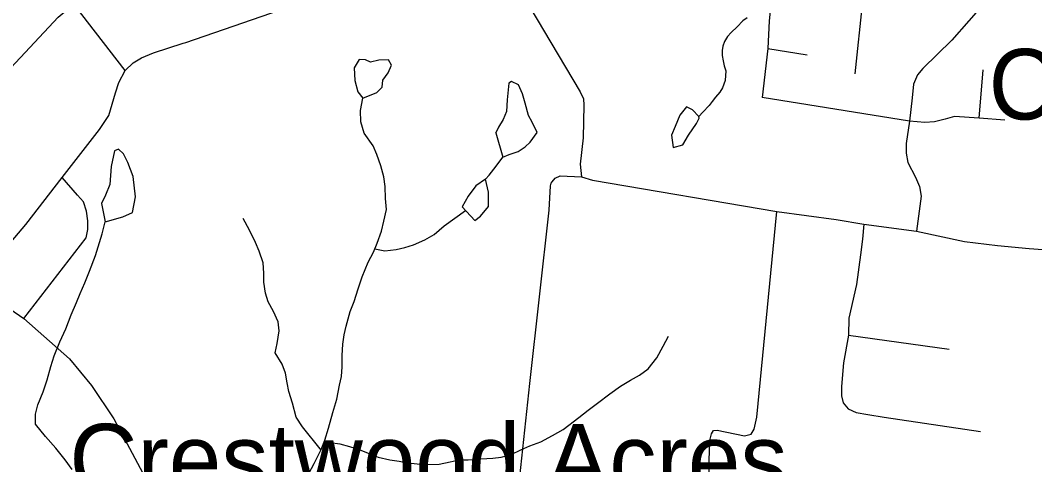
# Model space of a CAD drawing. Extents: x 0 to 69.5, y -4.5 to 22.
# Drawn here: x 2.379 to 3.515, y 16.285 to 16.783 of the extents above; entities that cross this region are included whole.
import ezdxf

# ---------------------------------------------------------------- set-up
doc = ezdxf.new("R2010")
doc.units = 0
for name, color, linetype in [('GM_X_County_Road', 7, 'Continuous'), ('GM_X_Interstate_Route', 7, 'Continuous'), ('GM_X_Minor_Lake', 7, 'Continuous'), ('GM_X_Minor_River', 7, 'Continuous'), ('GM_X_Township_Subdivision', 7, 'Continuous'), ('GM_X_Unincorporated_Text', 7, 'Continuous')]:
    doc.layers.add(name, color=color, linetype=linetype)

msp = doc.modelspace()

# ---------------------------------------------------------------- linework, layer by layer
at = {"layer": 'GM_X_County_Road'}
for points in [[(2.5645, 16.7579), (2.6921, 16.8018), (2.7129, 16.8072), (2.7415, 16.8122), (2.8434, 16.8208), (2.8888, 16.8307), (2.925, 16.8393)], [(2.925, 16.8393), (3.0063, 16.7023), (3.0099, 16.6947), (3.0101, 16.6874), (3.0094, 16.6508), (3.0062, 16.6215), (3.0077, 16.6072)], [(2.4966, 16.7263), (2.4393, 16.8007), (2.4357, 16.8056)], [(2.3395, 16.5036), (2.3546, 16.5175), (2.3853, 16.5537), (2.4262, 16.6065), (2.4679, 16.6603), (2.4783, 16.676), (2.4859, 16.7014), (2.4895, 16.7128), (2.4966, 16.7263), (2.5057, 16.7348), (2.5149, 16.7406), (2.5283, 16.7461), (2.5618, 16.757), (2.5645, 16.7579)], [(2.3831, 16.4487), (2.4531, 16.5388), (2.4547, 16.5483), (2.4548, 16.5581), (2.4534, 16.5688), (2.4501, 16.5791), (2.4433, 16.5867), (2.4262, 16.6065)], [(2.8559, 15.3242), (2.8828, 15.5776), (2.8823, 15.5871), (2.88, 15.6009), (2.8808, 15.6183), (2.8941, 15.7652), (2.913, 15.9963), (2.9286, 16.1743), (2.9306, 16.1979), (2.9499, 16.3756), (2.9714, 16.57), (2.9729, 16.5972), (2.9738, 16.6003), (2.9747, 16.6018), (2.978, 16.6059), (2.9836, 16.6083), (3.0077, 16.6072)], [(3.0077, 16.6072), (3.0199, 16.6034), (3.2263, 16.5685), (3.2928, 16.5595), (3.3237, 16.5541), (3.3826, 16.5464), (3.4363, 16.5348), (3.4732, 16.5304), (3.5089, 16.527), (3.5443, 16.5245), (3.6987, 16.5072), (3.6996, 16.5071)], [(3.2878, 15.9702), (3.2906, 16.01), (3.287, 16.0204), (3.2811, 16.0285), (3.1838, 16.1424), (3.1651, 16.1641), (3.1565, 16.1802), (3.1523, 16.1945), (3.1498, 16.2167), (3.1509, 16.3102), (3.153, 16.3194), (3.1554, 16.3229), (3.1594, 16.3234), (3.1901, 16.3171), (3.1974, 16.3189), (3.2011, 16.3245), (3.2039, 16.3381), (3.2263, 16.5685)], [(2.2074, 16.5345), (2.2273, 16.5312), (2.2755, 16.511), (2.3238, 16.4892), (2.3831, 16.4487), (2.4345, 16.4035), (2.4589, 16.3735), (2.484, 16.336), (2.5458, 16.2199), (2.6419, 16.0249), (2.6836, 15.948), (2.7291, 15.8843), (2.758, 15.8531), (2.7648, 15.8462)]]:
    msp.add_lwpolyline(points, dxfattribs=at)
at = {"layer": 'GM_X_Interstate_Route'}
msp.add_lwpolyline([(2.181, 16.4629), (2.2273, 16.5312), (2.2674, 16.589), (2.34, 16.6943), (2.3633, 16.7237), (2.4215, 16.7861), (2.4393, 16.8007), (2.4586, 16.8179), (2.4894, 16.8393), (2.7155, 16.9908), (2.8497, 17.0804), (2.9292, 17.1425), (3.0025, 17.2108), (3.0522, 17.2646), (3.1203, 17.3605), (3.2374, 17.5377), (3.2788, 17.5999), (3.3097, 17.642), (3.3406, 17.6772), (3.3886, 17.7251), (3.5019, 17.8134), (3.5855, 17.8769), (3.6539, 17.9292), (3.721, 17.9807)], dxfattribs=at)
at = {"layer": 'GM_X_Minor_Lake'}
for points in [[(2.7627, 16.6952), (2.7784, 16.7018), (2.7843, 16.7077), (2.7852, 16.7157), (2.7911, 16.7239), (2.7947, 16.7322), (2.7914, 16.7383), (2.7808, 16.7378), (2.7712, 16.7358), (2.7659, 16.7382), (2.7587, 16.7387), (2.7532, 16.7293), (2.754, 16.7152)], [(2.754, 16.7152), (2.7572, 16.7026), (2.7627, 16.6952)], [(2.9196, 16.6293), (2.9265, 16.6324), (2.9368, 16.6356), (2.9446, 16.6407), (2.95, 16.6459), (2.9578, 16.6568), (2.9524, 16.6683), (2.9484, 16.676), (2.9445, 16.6897), (2.9417, 16.7001), (2.937, 16.7104), (2.9291, 16.714), (2.9264, 16.7122), (2.9245, 16.6936), (2.9238, 16.6803), (2.9198, 16.6713), (2.9147, 16.6627), (2.9115, 16.6563)], [(2.9196, 16.6293), (2.9265, 16.6324), (2.9368, 16.6356), (2.9446, 16.6407), (2.95, 16.6459), (2.9578, 16.6568), (2.9524, 16.6683), (2.9484, 16.676), (2.9445, 16.6897), (2.9417, 16.7001), (2.937, 16.7104), (2.9291, 16.714), (2.9264, 16.7122), (2.9245, 16.6936), (2.9238, 16.6803), (2.9198, 16.6713), (2.9147, 16.6627), (2.9116, 16.6566)], [(3.139, 16.6747), (3.132, 16.6822), (3.1252, 16.6857), (3.1178, 16.6764)], [(3.1178, 16.6764), (3.1126, 16.6636), (3.1085, 16.6538), (3.1101, 16.6401), (3.1212, 16.6429), (3.1275, 16.6538), (3.1362, 16.6669), (3.1393, 16.6729), (3.139, 16.6747)], [(2.9116, 16.6566), (2.9196, 16.6293)], [(2.4743, 16.5569), (2.4939, 16.5626), (2.505, 16.5673), (2.5084, 16.5847), (2.5055, 16.6076), (2.4998, 16.6233), (2.4947, 16.6329), (2.4891, 16.6383), (2.4849, 16.6365), (2.4811, 16.6188), (2.4795, 16.5987), (2.4747, 16.5866), (2.4703, 16.5772)], [(2.8893, 16.5971), (2.8807, 16.5856), (2.8739, 16.5736), (2.888, 16.5584), (2.8946, 16.5632), (2.9036, 16.574), (2.9035, 16.59), (2.9001, 16.6045)], [(2.9001, 16.6045), (2.8893, 16.5971)], [(2.4703, 16.5772), (2.4743, 16.5569)]]:
    msp.add_lwpolyline(points, dxfattribs=at)
at = {"layer": 'GM_X_Minor_River'}
for points in [[(3.193, 16.7854), (3.1883, 16.7821), (3.182, 16.7754), (3.175, 16.7691), (3.1711, 16.7643), (3.1679, 16.7587), (3.1659, 16.7538), (3.165, 16.7488), (3.1652, 16.7431), (3.1662, 16.737), (3.1675, 16.7316), (3.1693, 16.7259), (3.1686, 16.7152), (3.1654, 16.7069), (3.1626, 16.7021), (3.1578, 16.6965), (3.1539, 16.6916), (3.1504, 16.6872), (3.1433, 16.6798), (3.139, 16.6747)], [(2.7023, 16.2748), (2.7083, 16.2861), (2.7163, 16.3019), (2.7203, 16.3121), (2.7244, 16.3257), (2.7291, 16.3434), (2.7336, 16.3581), (2.7366, 16.3737), (2.7388, 16.3835), (2.7398, 16.3945), (2.7397, 16.4071), (2.7404, 16.4196), (2.7418, 16.4302), (2.744, 16.44), (2.7485, 16.4563), (2.753, 16.4676), (2.7575, 16.4819), (2.762, 16.4951), (2.7689, 16.5117), (2.7749, 16.523), (2.7789, 16.5331), (2.7838, 16.5463), (2.7863, 16.5577), (2.7893, 16.5705), (2.7881, 16.5831), (2.7877, 16.5964), (2.7864, 16.6071), (2.7829, 16.6197), (2.7783, 16.6324), (2.7743, 16.642), (2.7644, 16.656), (2.7606, 16.669), (2.7601, 16.6815), (2.7627, 16.6952)], [(2.9001, 16.6045), (2.9043, 16.6092), (2.9121, 16.6193), (2.9196, 16.6293)], [(2.7159, 16.3011), (2.7151, 16.3027), (2.6952, 16.3271), (2.6883, 16.3379), (2.6841, 16.3536), (2.6798, 16.3667), (2.6782, 16.3766), (2.6762, 16.3873), (2.6726, 16.3973), (2.6646, 16.41), (2.6667, 16.4206), (2.669, 16.4346), (2.6681, 16.4449), (2.6627, 16.4565), (2.6568, 16.4673), (2.6537, 16.4769), (2.652, 16.4891), (2.6519, 16.4993), (2.6511, 16.5108), (2.6468, 16.5238), (2.6425, 16.5338), (2.636, 16.5473), (2.6287, 16.5604)], [(2.7763, 16.5265), (2.7874, 16.5242), (2.8, 16.5258), (2.8099, 16.5282), (2.8195, 16.531), (2.8322, 16.5368), (2.8426, 16.5426), (2.8538, 16.5522), (2.8778, 16.5695)], [(2.4372, 16.2794), (2.4295, 16.2903), (2.4191, 16.3031), (2.4073, 16.3163), (2.3962, 16.3302), (2.3961, 16.3413), (2.399, 16.3519), (2.4047, 16.3665), (2.4092, 16.3798), (2.4134, 16.3949), (2.4171, 16.4066), (2.4236, 16.4224), (2.4304, 16.437), (2.4361, 16.4525), (2.4421, 16.4664), (2.4462, 16.4766), (2.4514, 16.4883), (2.4566, 16.5014), (2.4635, 16.5191), (2.4681, 16.5335), (2.471, 16.5433), (2.4743, 16.5569)], [(2.7198, 16.3108), (2.7263, 16.3096), (2.7369, 16.3082), (2.7479, 16.3053), (2.7588, 16.3016), (2.7686, 16.2976), (2.7799, 16.2931), (2.7931, 16.2901), (2.8034, 16.2887), (2.8132, 16.287), (2.8238, 16.2856), (2.8348, 16.2849), (2.8481, 16.2854), (2.8607, 16.2881), (2.8706, 16.2901), (2.8809, 16.2903), (2.895, 16.2914), (2.9083, 16.2919), (2.9178, 16.2932), (2.9289, 16.2963), (2.9397, 16.3014), (2.9497, 16.3057), (2.962, 16.3103), (2.975, 16.3173), (2.987, 16.3242), (3.0048, 16.3378), (3.0149, 16.3459), (3.0257, 16.3537), (3.0393, 16.364), (3.0513, 16.3728), (3.0624, 16.3794), (3.0725, 16.3849), (3.0821, 16.3922), (3.0919, 16.4045), (3.0991, 16.4177), (3.1051, 16.4289)]]:
    msp.add_lwpolyline(points, dxfattribs=at)
at = {"layer": 'GM_X_Township_Subdivision'}
for points in [[(3.2267, 16.9013), (3.2264, 16.898), (3.2266, 16.87), (3.2207, 16.8119), (3.2179, 16.7821), (3.2161, 16.7511), (3.2099, 16.6961)], [(3.8766, 16.8608), (3.8386, 16.8639), (3.6602, 16.8815), (3.5812, 16.8884), (3.5665, 16.887), (3.553, 16.8832), (3.541, 16.877), (3.5216, 16.8628), (3.4605, 16.8035), (3.4221, 16.7604), (3.3897, 16.7285), (3.3838, 16.7214), (3.3793, 16.711), (3.3779, 16.6956), (3.3748, 16.6696), (3.3712, 16.6447), (3.371, 16.6339), (3.3731, 16.6233), (3.3815, 16.607), (3.3861, 16.5965), (3.388, 16.5857), (3.3826, 16.5464)], [(3.3142, 16.7228), (3.3227, 16.804), (3.3281, 16.8554)], [(3.2161, 16.7511), (3.2604, 16.7439)], [(3.453, 16.6729), (3.4573, 16.7272)], [(3.4816, 16.6706), (3.453, 16.6729), (3.4251, 16.6747), (3.4147, 16.6718), (3.4027, 16.669), (3.3922, 16.6681), (3.3833, 16.6689), (3.3748, 16.6696), (3.2099, 16.6961)], [(3.3237, 16.5541), (3.3221, 16.5374), (3.3199, 16.5197), (3.3155, 16.4865), (3.307, 16.449), (3.3067, 16.43), (3.301, 16.399), (3.2988, 16.3725), (3.2988, 16.3618), (3.3007, 16.3539), (3.3063, 16.3472), (3.3152, 16.3431), (3.3281, 16.3409), (3.3465, 16.3381), (3.4545, 16.322)], [(3.3067, 16.43), (3.4194, 16.4142)]]:
    msp.add_lwpolyline(points, dxfattribs=at)

# ---------------------------------------------------------------- texts
at = {"layer": 'GM_X_Unincorporated_Text'}
for s, p in [('Colerain Heights', (3.4634, 16.6715)), ('Crestwood Acres', (2.4342, 16.2515))]:
    msp.add_text(s, height=0.078977, rotation=0, dxfattribs=at).set_placement(p)

doc.saveas('drawing.dxf')
